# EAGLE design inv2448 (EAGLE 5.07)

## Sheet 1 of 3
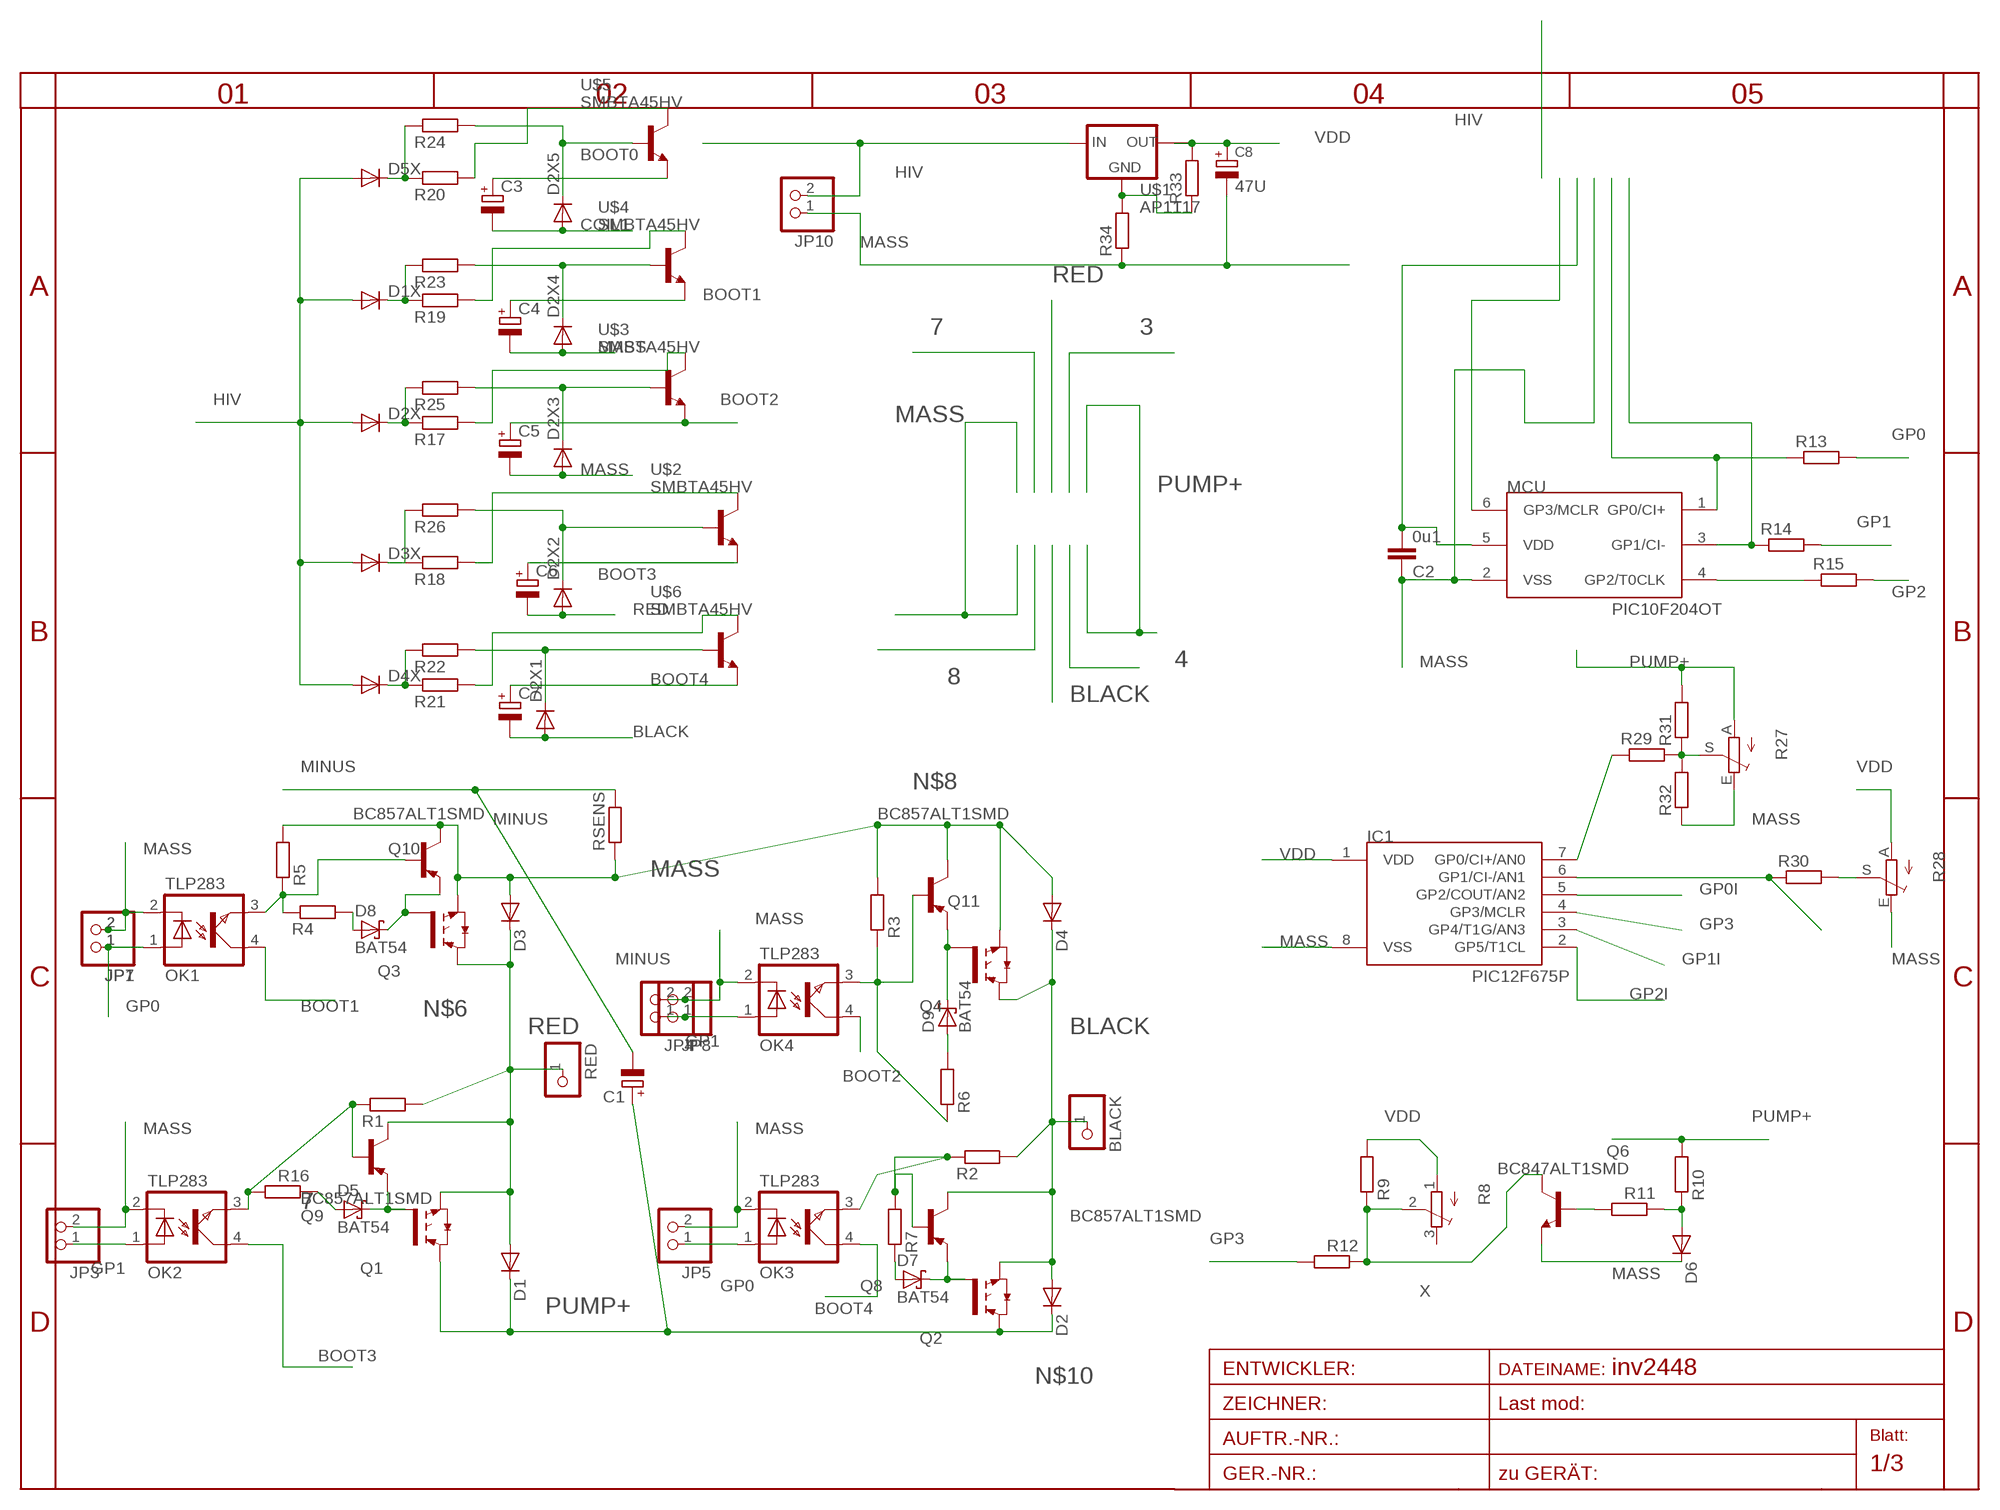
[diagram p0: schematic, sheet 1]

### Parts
BLACK  PINHD-1X14.5MM  [1X4MM5]
C1  CPOL-EUE5-13  [E5-13]
C2  0u1  C-EUC0805  [C0805]
C3  CPOL-EUE  [PANASONIC_E]
C4  CPOL-EUE  [PANASONIC_E]
C5  CPOL-EUE  [PANASONIC_E]
C6  CPOL-EUE  [PANASONIC_E]
C7  CPOL-EUE  [PANASONIC_E]
C8  47U  CPOL-EUC  [PANASONIC_C]
D1  DIODE-SMC  [SMC]
D1X  DIODE-SMA-DO214  [SMA-DO214AC]
D2  DIODE-SMC  [SMC]
D2X  DIODE-SMA-DO214  [SMA-DO214AC]
D2X1  DIODE-MINIMELF  [MINIMELF]
D2X2  DIODE-MINIMELF  [MINIMELF]
D2X3  DIODE-MINIMELF  [MINIMELF]
D2X4  DIODE-MINIMELF  [MINIMELF]
D2X5  DIODE-MINIMELF  [MINIMELF]
D3  DIODE-SMC  [SMC]
D3X  DIODE-SMA-DO214  [SMA-DO214AC]
D4  DIODE-SMC  [SMC]
D4X  DIODE-SMA-DO214  [SMA-DO214AC]
D5  BAT54  [SOT23]
D5X  DIODE-SMA-DO214  [SMA-DO214AC]
D6  DIODE-MINIMELF  [MINIMELF]
D7  BAT54  [SOT23]
D8  BAT54  [SOT23]
D9  BAT54  [SOT23]
IC1  PIC12F675P  [DIL8]
JP1  PINHD-1X2STR  [1X02]
JP3  PINHD-1X2STR  [1X02]
JP4  PINHD-1X2STR  [1X02]
JP5  PINHD-1X2STR  [1X02]
JP7  PINHD-1X2STR  [1X02]
JP8  PINHD-1X2STR  [1X02]
JP10  PINHD-1X2STR  [1X02]
MCU  PIC10F204OT  [SOT23-6]
OK1  TLP283  TLP283FLAT  [FLAT-4]
OK2  TLP283  TLP283FLAT  [FLAT-4]
OK3  TLP283  TLP283FLAT  [FLAT-4]
OK4  TLP283  TLP283FLAT  [FLAT-4]
Q1  IRG4BC15UD-S  [D2PACK]
Q2  IRG4BC15UD-S  [D2PACK]
Q3  IRG4BC15UD-S  [D2PACK]
Q4  IRG4BC15UD-S  [D2PACK]
Q6  BC847ALT1SMD  [SOT23]
Q8  BC857ALT1SMD  [SOT23-BEC]
Q9  BC857ALT1SMD  [SOT23-BEC]
Q10  BC857ALT1SMD  [SOT23-BEC]
Q11  BC857ALT1SMD  [SOT23-BEC]
R1  R-EU_R1206  [R1206]
R2  R-EU_R1206  [R1206]
R3  R-EU_R1206  [R1206]
R4  R-EU_R0805  [R0805]
R5  R-EU_R1206  [R1206]
R6  R-EU_R1206  [R1206]
R7  R-EU_R1206  [R1206]
R8  TRIM_EU-3223W  [3223W]
R9  R-EU_R1206  [R1206]
R10  R-EU_R1206  [R1206]
R11  R-EU_R1206  [R1206]
R12  R-EU_0204/7  [0204/7]
R13  R-EU_R0805  [R0805]
R14  R-EU_0207/10  [0207/10]
R15  R-EU_0207/20  [0207/20]
R16  R-EU_R1206  [R1206]
R17  R-EU_R1206  [R1206]
R18  R-EU_R1206  [R1206]
R19  R-EU_R1206  [R1206]
R20  R-EU_R1206  [R1206]
R21  R-EU_R1206  [R1206]
R22  R-EU_R1206  [R1206]
R23  R-EU_R1206  [R1206]
R24  R-EU_R1206  [R1206]
R25  R-EU_R1206  [R1206]
R26  R-EU_R1206  [R1206]
R27  TRIM_EU-RAND160  [RANDL]
R28  TRIM_EU-RAND160  [RANDL]
R29  R-EU_0207/30  [0207/30]
R30  R-EU_R0805  [R0805]
R31  R-EU_0207/30  [0207/30]
R32  R-EU_R0805  [R0805]
R33  R-EU_R0805  [R0805]
R34  R-EU_R0805  [R0805]
RED  PINHD-1X14.5MM  [1X4MM5]
RSENS  R-EU_CERAM50  [CERAM50]
U$1  AP1117  [SOT223]
U$2  SMBTA45HV  [SOT23HV]
U$3  SMBTA45HV  [SOT23HV]
U$4  SMBTA45HV  [SOT23HV]
U$5  SMBTA45HV  [SOT23HV]
U$6  SMBTA45HV  [SOT23HV]

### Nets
3: OK1.3(EMIT) Q10.B R4.1 R5.1
4: OK3.3(EMIT) Q8.B R2.1 R7.2
7: OK2.3(EMIT) Q9.B R1.1 R16.2
BLACK: BLACK.1 C7.- D2.A D2X1.A D4.C Q2.3(E) Q4.2(C) Q8.C R2.2
BOOT0: C3.+ U$5.2(E) ; also sheet 2
BOOT1: C4.+ OK1.4(COL) U$4.2(E)
BOOT2: C5.+ OK4.4(COL) U$3.2(E)
BOOT3: C6.+ OK2.4(COL) U$2.2(E)
BOOT4: C7.+ OK3.4(COL) U$6.2(E)
COIL1: C3.- D2X5.A ; also sheet 2
GP0: JP1.1 JP5.1 JP7.1 OK1.1(A) OK3.1(A) R13.2
GP0I: IC1.5(GP2/COUT/AN2) MCU.1(GP0/CI+) R13.1
GP1: JP3.1 JP4.1 JP8.1 OK2.1(A) OK4.1(A) R14.2
GP1I: IC1.3(GP4/T1G/AN3) MCU.3(GP1/CI-) R14.1
GP2: R15.2 ; also sheet 2
GP2I: IC1.2(GP5/T1CL) MCU.4(GP2/T0CLK) R15.1
GP3: IC1.4(GP3/MCLR) MCU.6(GP3/MCLR) R12.2
HIV: D1X.A D2X.A D3X.A D4X.A D5X.A JP10.2 U$1.3(IN) ; also sheet 2
MASS: C2.1 C4.- C5.- C8.- D2X3.A D2X4.A D3.A D4.A D6.C IC1.8(VSS) JP1.2 JP3.2 JP4.2 JP5.2 JP7.2 JP8.2 JP10.1 MCU.2(VSS) OK1.2(C) OK2.2(C) OK3.2(C) OK4.2(C) Q3.3(E) Q4.3(E) Q6.2(E) Q10.C Q11.C R3.2 R5.2 R27.E R28.E R32.1 R34.1 RSENS.1 ; also sheet 2
MINUS: C1.- RSENS.2 ; also sheet 2,3
N$2: D8.1(A) R4.2
N$4: D6.A R10.1 R11.1
N$5: Q6.1(B) R11.2
N$6: D8.3(C) Q3.1(G) Q10.E
N$7: D9.3(C) Q4.1(G) Q11.E
N$8: OK4.3(EMIT) Q11.B R3.1 R6.1
N$9: D9.1(A) R6.2
N$10: D7.3(C) Q2.1(G) Q8.E
N$11: D7.1(A) R7.1
N$12: D5.1(A) R16.1
N$13: D3X.K(C) R18.1 R26.1
N$14: D5.3(C) Q1.1(G) Q9.E
N$15: D4X.K(C) R21.1 R22.1
N$16: D2X.K(C) R17.1 R25.1
N$17: D1X.K(C) R19.1 R23.1
N$18: D5X.K(C) R20.1 R24.1
N$19: D2X1.C R22.2 U$6.1(B)
N$20: D2X5.C R24.2 U$5.1(B)
N$21: D2X4.C R23.2 U$4.1(B)
N$22: D2X2.C R26.2 U$2.1(B)
N$23: D2X3.C R25.2 U$3.1(B)
N$24: R28.S R30.2
N$25: R18.2 U$2.3(C)
N$26: R21.2 U$6.3(C)
N$27: R17.2 U$3.3(C)
N$28: R20.2 U$5.3(C)
N$29: R19.2 U$4.3(C)
N$30: R33.1 R34.2 U$1.1(GND)
N$31: IC1.6(GP1/CI-/AN1) R30.1
N$34: R27.S R29.2 R31.1 R32.2
N$35: IC1.7(GP0/CI+/AN0) R29.1
PUMP+: C1.+ D1.C D2.C Q1.2(C) Q2.2(C) R10.2 R27.A R31.2 ; also sheet 2,3
RED: C6.- D1.A D2X2.A D3.C Q1.3(E) Q3.2(C) Q9.C R1.2 RED.1
VDD: C2.2 C8.+ IC1.1(VDD) MCU.5(VDD) R8.1(A) R9.2 R28.A R33.2 U$1.2(OUT) U$1.4(TAB)
X: Q6.3(C) R8.2(S) R9.1 R12.1
Unconnected: R8.3(E)

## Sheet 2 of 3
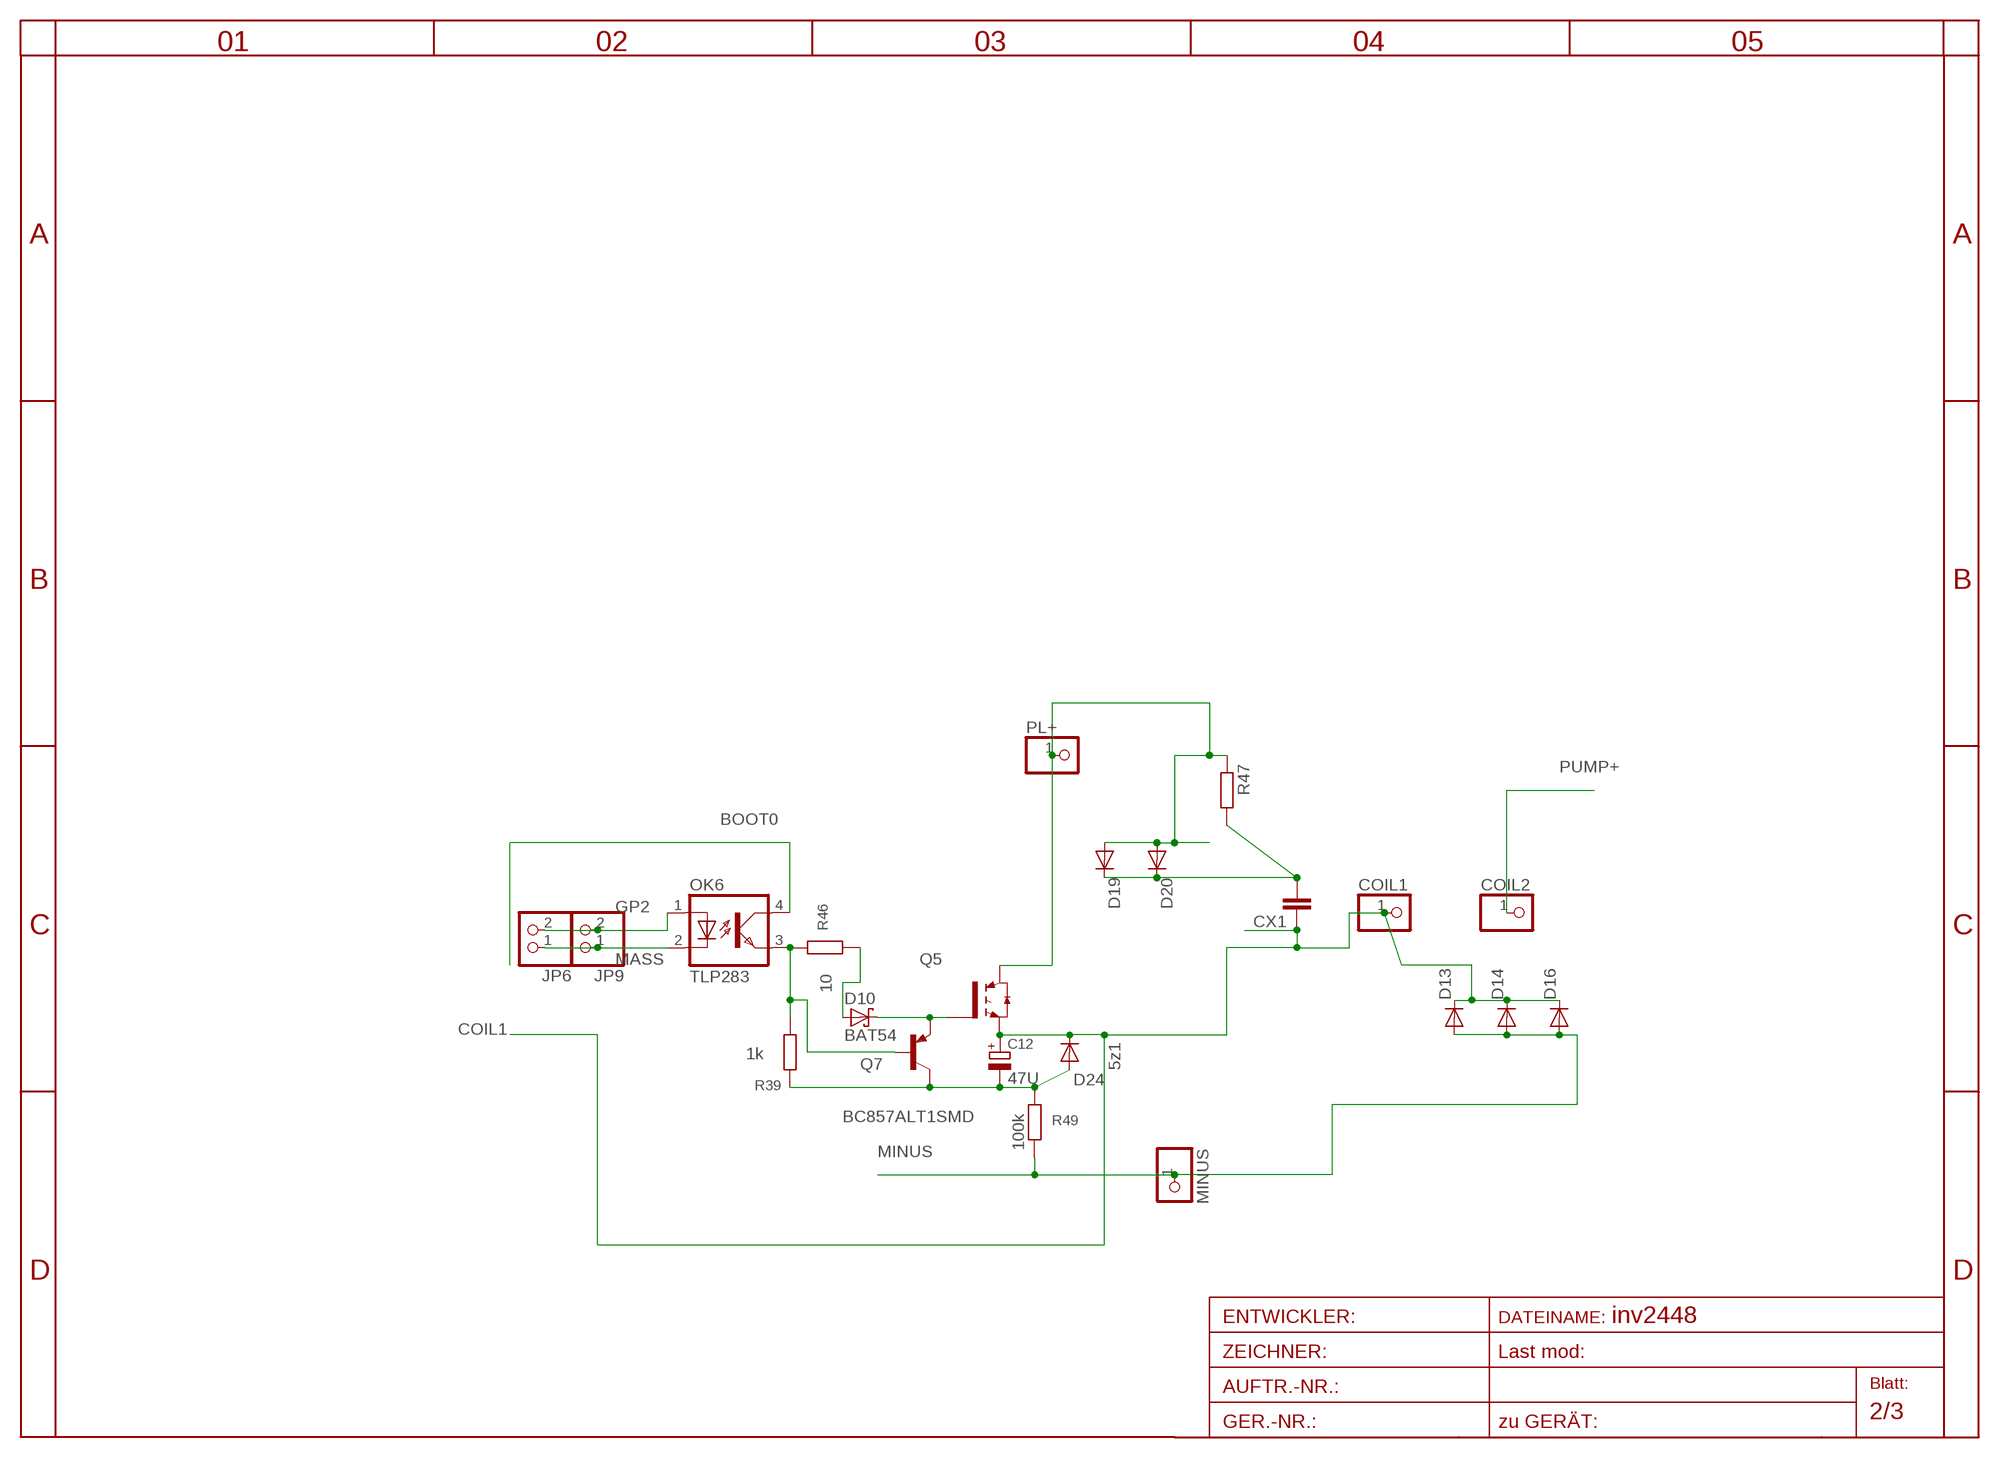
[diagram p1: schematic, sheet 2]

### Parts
C12  47U  CPOL-EUSMCA  [SMC_A]
COIL1  PINHD-1X14.5MM  [1X4MM5]
COIL2  PINHD-1X14.5MM  [1X4MM5]
CX1  CXXC22B10  [XC22B10]
D10  BAT54  [SOT23]
D13  DIODE-SMC  [SMC]
D14  DIODE-SMC  [SMC]
D16  DIODE-SMC  [SMC]
D19  DIODE-SMC  [SMC]
D20  DIODE-SMC  [SMC]
D24  5z1  DIODE-MINIMELF  [MINIMELF]
JP6  PINHD-1X2STR  [1X02]
JP9  PINHD-1X2STR  [1X02]
MINUS  PINHD-1X14.5MM  [1X4MM5]
OK6  TLP283  TLP283FLAT  [FLAT-4]
PL+  PINHD-1X14.5MM  [1X4MM5]
Q5  IRG4BC15UD-S  [D2PACK]
Q7  BC857ALT1SMD  [SOT23-BEC]
R39  1k  R-EU_R1206  [R1206]
R46  10  R-EU_R1206  [R1206]
R47  R-EU_0207/5V  [0207/5V]
R49  100k  R-EU_R1206  [R1206]

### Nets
BATT-: C12.- D24.A Q7.C R39.1 R49.2
BOOT0: OK6.4(COL) ; also sheet 1
COIL1: C12.+ COIL1.1 CX1.1 D13.C D14.C D16.C D24.C Q5.3(E) ; also sheet 1
GP2: JP6.2 JP9.2 OK6.1(A) ; also sheet 1
HIV: D19.A D20.A PL+.1 Q5.2(C) R47.1 ; also sheet 1
MASS: JP6.1 JP9.1 OK6.2(C) ; also sheet 1
MINUS: D13.A D14.A D16.A MINUS.1 R49.1 ; also sheet 1,3
N$1: D10.3(C) Q5.1(G) Q7.E
N$3: D10.1(A) R46.1
N$43: OK6.3(EMIT) Q7.B R39.2 R46.2
PUMP+: COIL2.1 ; also sheet 1,3
SNUB: CX1.2 D19.C D20.C R47.2

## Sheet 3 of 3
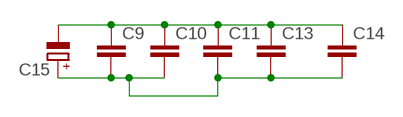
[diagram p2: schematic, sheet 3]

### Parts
C9  C-EUC1206  [C1206]
C10  C-EUC1206  [C1206]
C11  C-EUC1206  [C1206]
C13  C-EUC1206  [C1206]
C14  C-EUC1206  [C1206]
C15  CPOL-EUE2.5-7  [E2,5-7]

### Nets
MINUS: C9.1 C10.1 C11.1 C13.1 C14.1 C15.- ; also sheet 1,2
PUMP+: C9.2 C10.2 C11.2 C13.2 C14.2 C15.+ ; also sheet 1,2

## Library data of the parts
BLACK COIL1 COIL2 MINUS PL+ RED = pinhead:PINHD-1X1: PIN HEADER
C1 C3-C7 C15 = rcl:CPOL-EU: POLARIZED CAPACITOR, European symbol
C2 C9-C11 C13 C14 = rcl:C-EU: CAPACITOR, European symbol
C8 C12 = rcl-2:CPOL-EU: POLARIZED CAPACITOR, European symbol
CX1 = rcl:CX: X CAPACITOR
D1 D1X D2 D2X D2X1-D2X5 D3 D3X D4 D4X D5X D6 D13 D14 D16 D19 D20 D24 = diode:DIODE-: DIODE
D5 D7-D10 = diode:BAT54: Schottky Diodes
IC1 = microchip-5:PIC12F6*: uPC nW 1k Program Flash memory 2x Timer Comparator 10b A/D converter/ 4xIN
JP1 JP3-JP10 = pinhead:PINHD-1X2: PIN HEADER
MCU = microchip-3:PIC10F2*: uPC nW 0,25/0,5k Program Flash memory Comparator
OK1-OK4 OK6 = optocoupler:TLP283: TOSHIBA PHOTOCOUPLER GaAs IRED & PHOTO-TRANSISTOR Source: http://www.semicon.toshiba.co.jp/td/en/Opto/Photocoupler/en_20050928_TLP283_datasheet.pdf
Q1-Q5 = transistor-power:IRG4BC15UD-: INSULATED GATE BIPOLAR TRANSISTOR WITH ULTRAFAST SOFT RECOVERY DIODE
Q6 = transistor-npn:BC847*: NPN Transistor
Q7-Q11 = transistor-pnp:BC857*: PNP Transistror
R1-R7 R9-R12 R16-R26 R47 RSENS = rcl:R-EU_: RESISTOR, European symbol
R8 R27 R28 = pot:TRIM_EU-: POTENTIOMETER
R13-R15 R29-R34 R39 R46 R49 = rcl-2:R-EU_: RESISTOR, European symbol
U$1 = v-reg:AP1117
U$2-U$6 = transistor-npn:SMBTA45

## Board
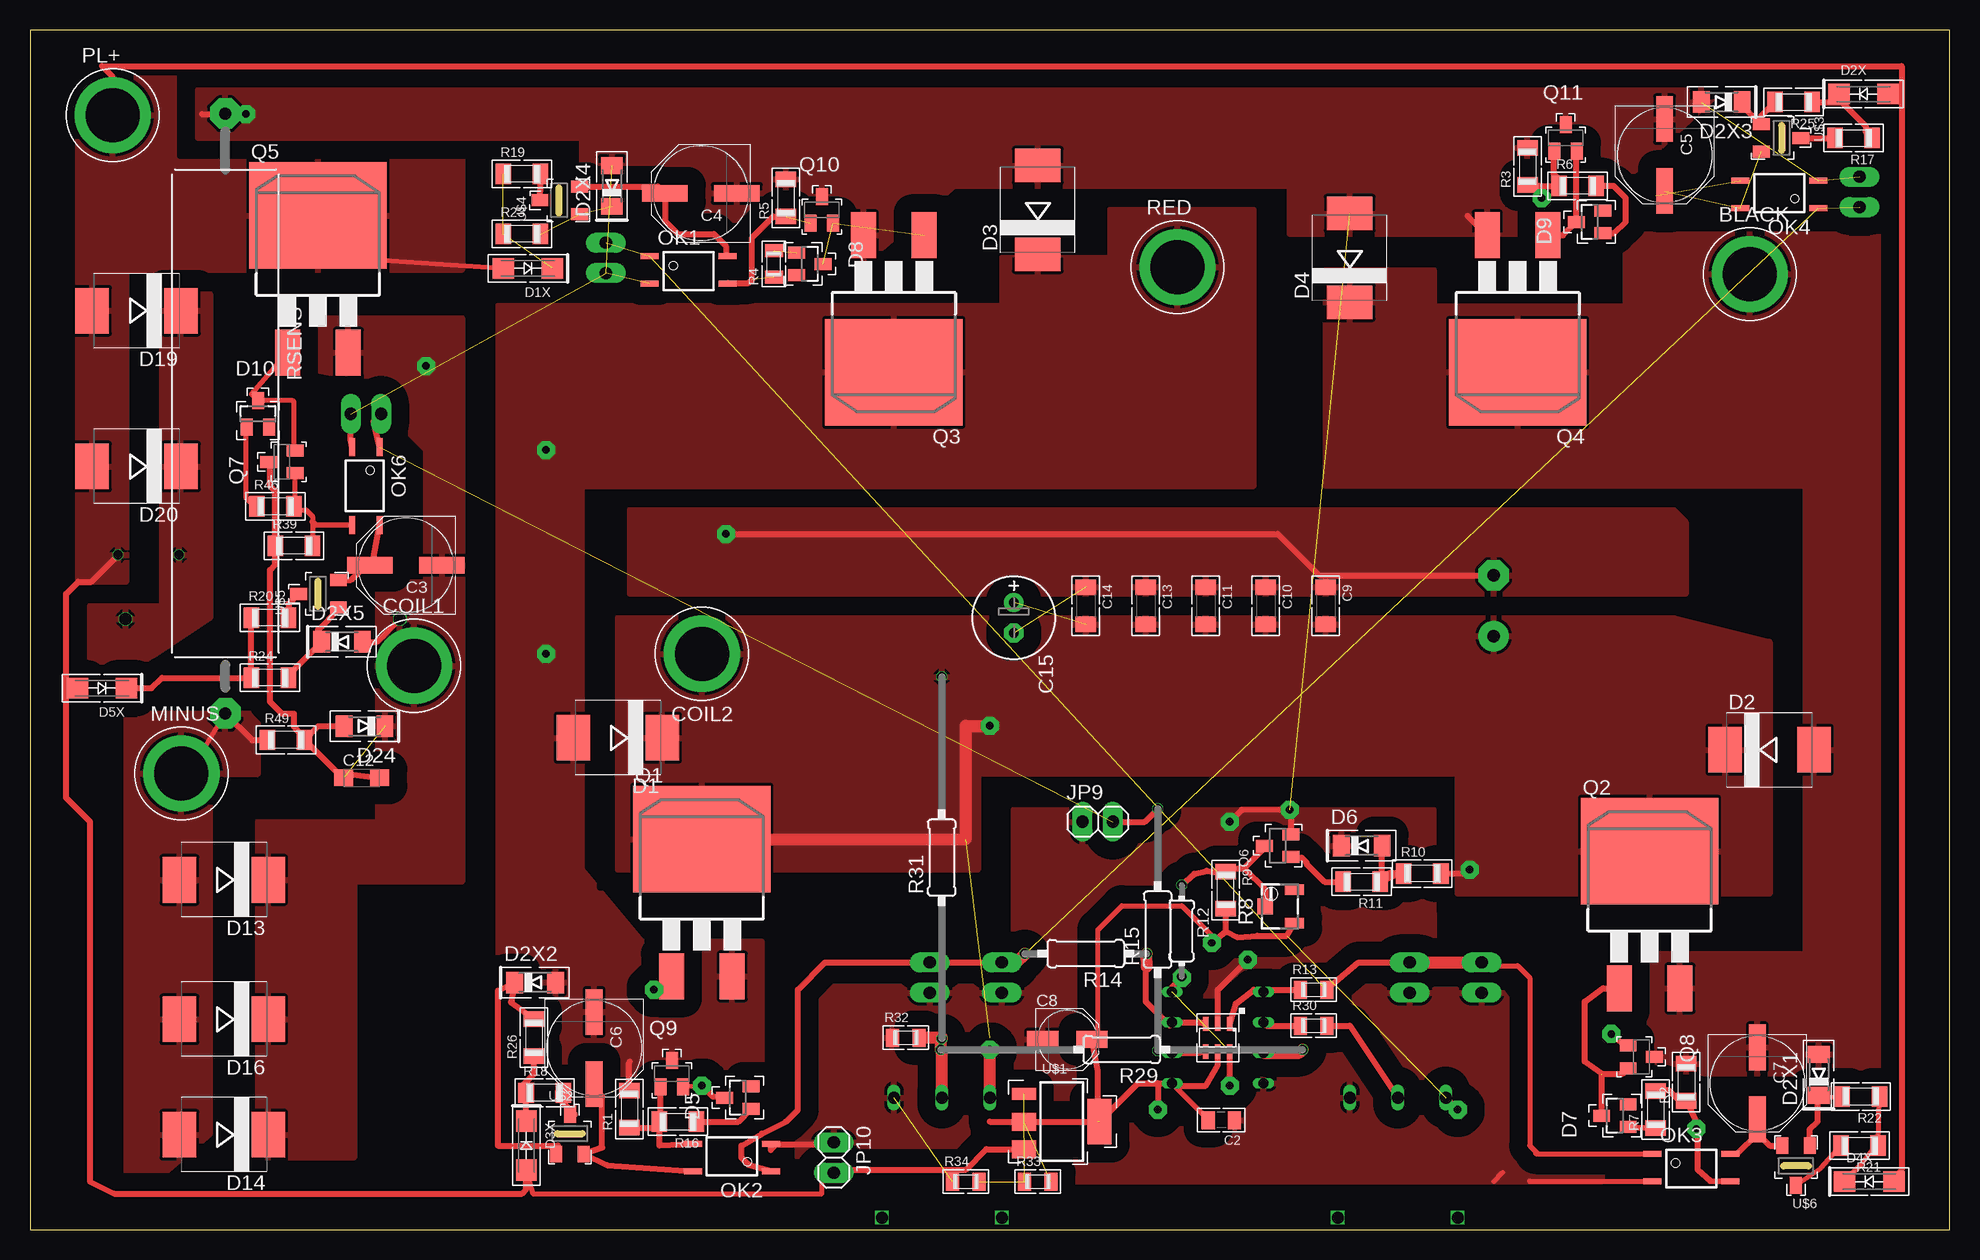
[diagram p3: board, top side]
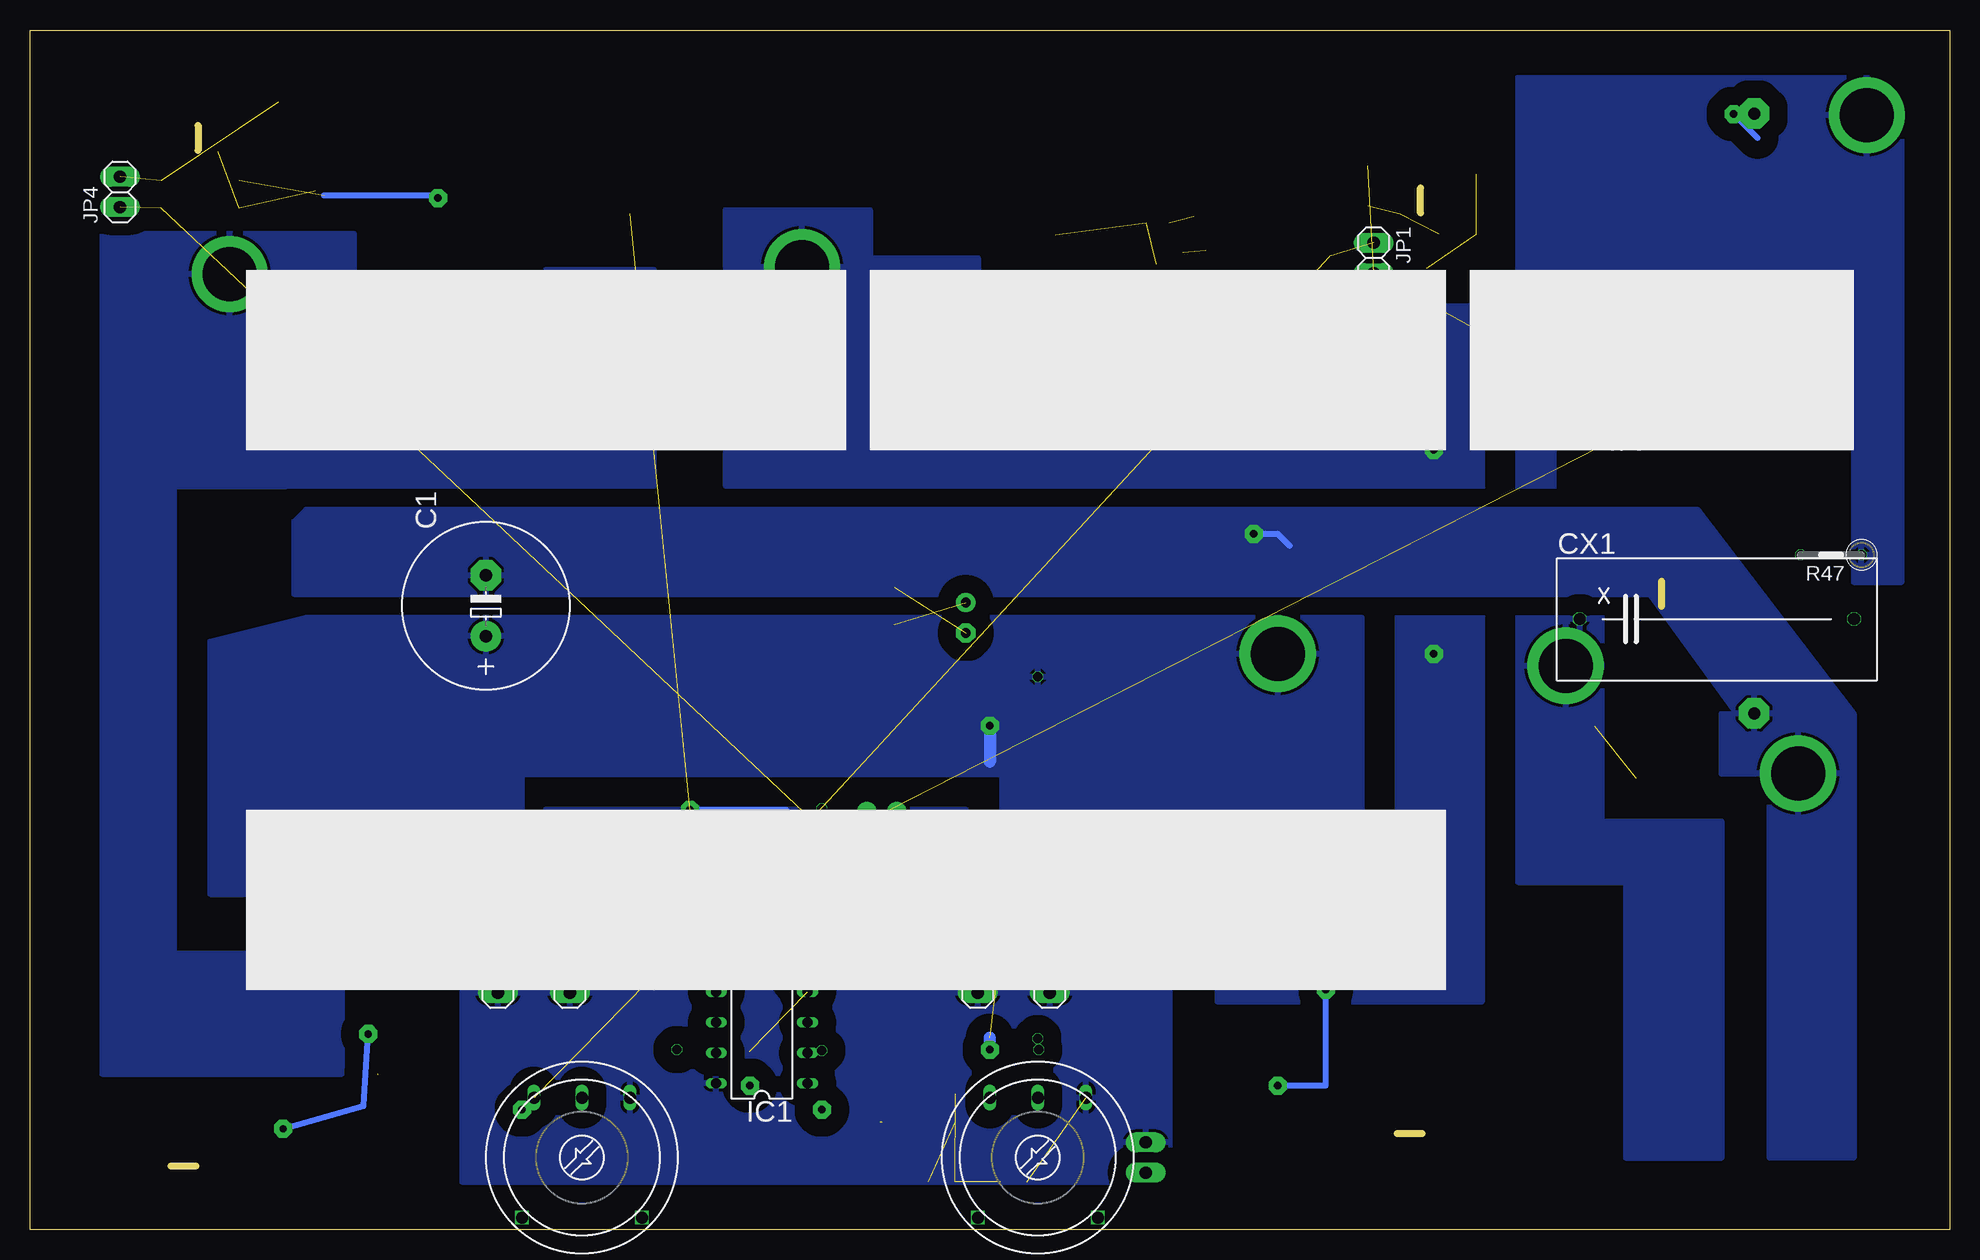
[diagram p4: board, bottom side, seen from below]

Size 160 x 100 mm. Coordinates in mm from the lower left corner, seen from the top.
Outline: 0,0 160,0 160,100 0,100 0,0
Copper layers (1*16): Top 0.035mm / dielectric 1.5mm / Bottom 0.035mm
Design rules "default": minimum track width 10mil, minimum drill 20mil, track to track 8mil, track to pad 8mil, pad to pad 8mil, via to via 8mil, smd to smd 8mil, copper to edge 40mil, drill to drill 8mil, minimum pad ring 1mil, minimum via ring 8mil, stop-mask expansion 4mil, vias tented up to drill 0mil, thermal gap 10mil

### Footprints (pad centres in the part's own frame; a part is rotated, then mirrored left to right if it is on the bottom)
1X4MM5 = drill 4.5 pad 6.35 round: 1 0,0
E5-13 = drill 1.016 pad 2.54 round: + -2.54,0 | drill 1.016 pad 2.54 octagon: - 2.54,0
C0805 = smd 1.1 x 1.5: 1 -1.1,0; 2 1.1,0
PANASONIC_E = smd 3.8 x 1.4: + 3,0; - -3,0
PANASONIC_C = smd 2.6 x 1.4: + 2.05,0; - -2.05,0
C1206 = smd 1.3 x 1.7: 1 -1.55,0; 2 1.55,0
SMC_A = smd 1.6 x 1.4: + -1.5,0; - 1.5,0
E2,5-7 = drill 0.813 pad 1.6 round: + -1.27,0 | drill 0.813 pad 1.6 octagon: - 1.27,0
XC22B10 = drill 1.016 octagon: 1 -11.43,0.025; 2 11.43,0.025
SMC = smd 2.8 x 3.8: A 3.7,0; C -3.7,0
SMA-DO214AC = smd 1.8 x 1.7: A 2.05,-0.127; K -2.05,-0.127
MINIMELF = smd 1.4 x 1.8: A 1.7,0; C -1.7,0
SOT23 = smd 1 x 1.4: 1 -0.95,-1.1; 2 0.95,-1.1; 3 0,1.1
DIL8 = drill 0.8 long: 1 -3.81,-3.81; 2 -1.27,-3.81; 3 1.27,-3.81; 4 3.81,-3.81; 5 3.81,3.81; 6 1.27,3.81; 7 -1.27,3.81; 8 -3.81,3.81
1X02 = drill 1.016 pad 1.676 long: 1 -1.27,0; 2 1.27,0
SOT23-6 = smd 0.45 x 1.2: 1 -1.016,-1.15; 2 0,-1.15; 3 1.016,-1.15; 4 1.016,1.15; 5 0,1.15; 6 -1.016,1.15
FLAT-4 = smd 1.5 x 0.5: 1 -3.25,1.15; 2 -3.25,-1.15; 3 3.25,-1.15; 4 3.25,1.15
D2PACK = smd 2.083 x 3.81: 1 -2.54,-8.89; 3 2.54,-8.89 | smd 11.43 x 8.89: 2 0,2.54
SOT23-BEC = smd 1 x 1.4: B -0.95,-1.1; C 0,1.1; E 0.95,-1.1
R1206 = smd 1.3 x 1.7: 1 -1.55,0; 2 1.55,0
R0805 = smd 1.1 x 1.5: 1 -1.1,0; 2 1.1,0
3223W = smd 0.9 x 1.6: 1 -1.4,-1.215; 3 1.4,-1.215 | smd 1.3 x 1.3: 2 0,1.215
0204/7 = drill 0.813 octagon: 1 -3.81,0; 2 3.81,0
0207/10 = drill 0.813 octagon: 1 -5.08,0; 2 5.08,0
0207/20 = drill 0.813 octagon: 1 -10.08,0; 2 10.08,0
RANDL = drill 1 long: A -4,5; E 4,5; S 0,5 | drill 1 square: P$1 -5,-5; P$2 5,-5
0207/30 = drill 0.813 octagon: 1 -15.08,0; 2 15.08,0
0207/5V = drill 0.813 octagon: 1 -2.54,0; 2 2.54,0
CERAM50 = drill 1 pad 2.54 octagon: 1 -25,0; 2 25,0
SOT223 = smd 1 x 2: 1 -2.3,-3.15 | smd 1.5 x 2: 2 0,-3.15; 3 2.3,-3.15 | smd 3.8 x 2: 4 0,3.15
SOT23HV = smd 1 x 1.4: 1 -1.15,-1.7; 2 1.15,-1.7; 3 0,1.6

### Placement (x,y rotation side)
BLACK  143.35,79.64 0 top
C1  122,52 90 bottom
C2  99.3,9.12 180 top
C3  31.34,55.37 180 top
C4  55.92,86.38 180 top
C5  136.25,89.57 270 top
C6  47.02,15.13 270 top
C7  143.98,12.19 270 top
C8  86.46,15.85 0 top
C9  108,52 270 top
C10  103,52 270 top
C11  98,52 270 top
C12  27.65,37.66 0 top
C13  93,52 270 top
C14  88,52 270 top
C15  82,51 270 top
COIL1  32,47 0 top
COIL2  56,48 180 top
CX1  19.39,50.87 0 bottom
D1  49,41 180 top
D1X  41.5,80 180 top
D2  145,40 0 top
D2X  152.83,94.78 0 top
D2X1  149.1,12.9 90 top
D2X2  42.1,20.6 0 top
D2X3  141,94 180 top
D2X4  48.5,87 90 top
D2X5  26,49 0 top
D3  84,85 90 top
D3X  41.5,7 270 top
D4  110,81 90 top
D4X  153.31,4.12 0 top
D5  59,11 90 top
D5X  6,45 180 top
D6  111,32 0 top
D7  132.1,9.5 90 top
D8  65,80.5 270 top
D9  130,84 90 top
D10  19,68 0 top
D13  16.16,29.15 180 top
D14  16.16,7.91 180 top
D16  16.16,17.53 180 top
D19  8.88,76.59 180 top
D20  8.88,63.62 180 top
D24  27.89,41.96 180 top
IC1  99,16 90 bottom
JP1  48,81 270 bottom
JP3  75,21 270 bottom
JP4  152.5,86.5 90 bottom
JP5  121,21 270 bottom
JP6  28,68 180 bottom
JP7  115,21 270 bottom
JP8  81,21 270 bottom
JP9  89,34 0 top
JP10  67,6 270 top
MCU  99,16 180 top
MINUS  12.62,38.02 0 top
OK1  54.9,80 0 top
OK2  58.5,6 180 top
OK3  138.46,5.18 0 top
OK4  145.81,86.29 180 top
OK6  28,62 270 top
PL+  6.89,92.9 0 top
Q1  56,30 0 top
Q2  135,29 0 top
Q3  72,74 180 top
Q4  124,74 180 top
Q5  24,82 0 top
Q6  104,32 90 top
Q7  21,64 90 top
Q8  134.3,14.4 270 top
Q9  53.5,13 0 top
Q10  66,85 0 top
Q11  128,91 0 top
R1  49.95,10.05 90 top
R2  138.05,12.28 90 top
R3  124.83,88.62 90 top
R4  62,80.5 90 top
R5  63,86 90 top
R6  129,87 0 top
R7  135.5,10 90 top
R8  104.18,26.94 90 top
R9  99.67,28.3 270 top
R10  116.05,29.67 0 top
R11  111,29 180 top
R12  96,24.9 270 top
R13  107,20 0 top
R14  88,23 180 top
R15  94,25 90 top
R16  54,9 180 top
R17  152,91 180 top
R18  42.9,11.4 0 top
R19  41,88 0 top
R20  20,51 0 top
R21  152.5,7 180 top
R22  152.6,11.1 180 top
R23  41,83 0 top
R24  20,46 0 top
R25  147,94 180 top
R26  42,16 90 top
R27  76,6 0 bottom
R28  114,6 0 bottom
R29  91,15 180 top
R30  107,17 0 top
R31  76,31 90 top
R32  73,16 0 top
R33  84,4 0 top
R34  78,4 0 top
R39  22,57 0 top
R46  20.46,60.28 0 top
R47  9.88,56.24 180 bottom
R49  21.34,40.81 0 top
RED  95.65,80.23 0 top
RSENS  16.29,68.04 270 top
U$1  86,9 270 top
U$2  45,8 0 top
U$3  146,91 270 top
U$4  44.1,85.8 90 top
U$5  24,53 90 top
U$6  147.2,5.3 180 top

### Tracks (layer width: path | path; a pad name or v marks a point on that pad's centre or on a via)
3  (2 unrouted)
  Top 0.5: R5.1 61.95,84.45 60.2,82.7 60.2,79.2 59.9,78.9 58.2,78.9 OK1.3
4  (via drill 0.6 pad 1.5)
  Top 0.5: Q8.B 132.75,15.45 v131.8,16.3 | OK3.3 140.06,4.04 139,5 139,8.3 v138.9,8.4 138.9,8.98 R2.1 137.47,10.73 136.6,11.6 135.55,11.6 R7.2
  Bottom 0.5: v131.8,16.3 132.2,10.3 v138.9,8.4
7
  Top 0.5: R16.2 52.45,7 OK2.3 | R1.1 51.95,8.5 R16.2 | Q9.B 52.55,9.1 R16.2
BATT-
  Top 0.5: Q7.C 20,63.9 20,62 20.45,61.55 R39.1 20.45,55.45 20,55 20,44 21,43 22,43 22,41.92 R49.2 | D24.A 24.04,41.96 R49.2 | C12.- 25.6,38.1 R49.2
BLACK
  pour Top (isolate 1.5, rank 2): 108,80 117,80 117,77 133,77 133,83 154,83 154,13 134,13 134,23 148,23 148,62 108,62
  pour Bottom (isolate 1.5, rank 2): 108,80 117,80 117,77 133,77 133,83 154,83 154,13 134,13 134,23 148,23 148,62 108,62
BOOT0
  Top 0.5: 28.64,56.02 OK6.4 | 28.64,56.02 C3.+ | U$5.2 26.76,54.15 28.64,56.02
BOOT1
  Top 0.5: OK1.4 58,81.3 58,82 57,83 54,83 52.92,84.08 C4.+ 52.35,86.95 U$4.2
BOOT2  (2 unrouted)
BOOT3
  Top 0.5: OK2.4 48.09,5.37 U$2.2 47.7,6.85 47.7,11.1 47.02,11.78 C6.+
BOOT4
  Top 0.5: OK3.4 142.33,6.33 144,8 | 144,8 144,9.17 C7.+ | U$6.2 145,7 144,8
COIL1  (via drill 0.6 pad 1.5)  (1 unrouted)
  Top 0.5: D2X5.A 28.93,49 CX1.1
  other vias: 33,72
  pour Top (isolate 1.5, rank 2): 22,76 36,76 36,29 27,29 27,6 19,6 19,34 29,34 29,54 33,54 33,65 27,71 22,72
  pour Bottom (isolate 1.5, rank 2): 26,76 36,76 36,29 27,29 27,6 19,6 19,34 29,34 29,54 33,54 33,65 26,72
GP0  (2 unrouted)
  Top 0.406: 125.5,6.5 125,7 125,21 124,22 121.27,22 JP5.1 | 125.5,6.5 125.58,6.42 | OK3.1 125.5,6.33 125.5,6.5
  Top 0.5: R13.2 108,20 110.73,22.27 JP7.1
  Top 1: JP7.1 JP5.1
GP0I
  Top 0.5: MCU.1 100.52,18.82 102,20 102.62,20 IC1.5 103,20 R13.1
GP1  (2 unrouted)
  Top 0.5: 82.19,22.27 JP8.1 JP3.1 66.27,22.27 64,20 64,10 63,9 61,8 59.3,7 59.3,6 59.94,5.37 OK2.1
  Top 1: 82.19,22.27 R14.2
GP1I
  Top 0.5: MCU.3 97.6,17.27 IC1.3 95,17.08 95,17 93,19 93,21.9 93.1,21.9
  Top 1: 93.1,21.9 R14.1
GP2  (1 unrouted)
  Top 0.5: OK6.1 28.64,67.36 JP6.2 | JP9.2 92.92,34 R15.2
GP2I
  Top 0.5: MCU.4 97.36,14.73 IC1.2 95.19,14.81 95,15 94.08,15 R15.1
GP3  (via drill 0.6 pad 1.5)  (1 unrouted)
  Top 0.5: MCU.6 100.02,13.98 v100,12 | R12.2 96.2,21.2 v96,21 95.19,20.19 IC1.4
HIV
  Top 0.406: 66,5 66,3 41.9,3 D3X.A | 67,5 JP10.2 | D1X.A 27.62,80.92 Q5.2
  Top 0.5: D4X.A 155.44,4.44 156,5 156,95 | 156,95 156,97 6,97 6.89,96.11 PL+.1 | 3,45 3,36 5,34 5,4 7,3 41,3 41.37,3.37 D3X.A | 3,45 3,53 4,54 5.1,54 R47.1 | U$1.3 79.7,6.7 78,5 67,5 66,5 | D5X.A 3.13,45.13 3,45 | D2X.A 155.65,94.65 156,95
  pour Top (isolate 1.5, rank 2): 4,96 36,96 36,80 8,80 8,54 4,54
  pour Bottom (isolate 1.5, rank 2): 4,96 36,96 36,80 8,80 8,54 4,54
MASS  (via drill 0.6 pad 1.5)  (7 unrouted)
  Top 0.406: 122,4 122.75,4.75 | OK3.2 125,4.03 125,4
  Top 0.5: Q4.3 119.83,84.52 | MCU.2 99,20 v101.5,22.5 | Q6.2 105.1,34.9 v105,35 101,35 v100,34 | JP10.1 65.83,7.1 62.2,7.1 61.73,6.63 OK2.2 | JP6.1 26.73,65.88 OK6.2 | v18,93 14.33,93 RSENS.1
  Bottom 0.5: v105,35 97,35 92,30 | v18,93 16,91
  pour Top (isolate 1.5): 14,95 141,95 128,83 105,83 105,87 77,87 70,81 52,81 48,82 48,87 46,87 46,91 14,91
  pour Top (isolate 1.5, rank 3): 82,35 117,35 117,22 121,22 131,9 131,4 64,4 64,21 74,24 82,24
  pour Bottom (isolate 1.5, rank 3): 82,35 117,35 117,22 124,22 124,4 65,4 65,21 78,21 82,24
MINUS  (via drill 0.6 pad 1.5)  (1 unrouted)
  Top 0.406: RSENS.2 14.29,39.69 MINUS.1
  Top 0.5: C1.- 107.46,54.54 104,58 v58,58 | R49.1 18.52,40.81 RSENS.2
  Bottom 0.5: v58,58 56,58 55,57
  pour Top (isolate 1.5): 138,53 50,53 50,60 137,60 138,59
  pour Top (isolate 1.5, rank 3): 8,43 8,2 15,8 15,38 19,38 19,43
  pour Bottom (isolate 1.5): 8,43 21,60 60,60 60,53 25,53 17,42 9,42
  pour Bottom (isolate 1.5): 138,53 50,53 50,60 137,60 138,59
  pour Bottom (isolate 1.5, rank 3): 8,43 8,6 15,6 15,38 19,38 19,43
N$1
  Top 0.406: Q5.1 18.46,69.64 D10.3 21.9,69.1 22,69 22,65.05 Q7.E
N$2  (1 unrouted)
N$3
  Top 0.406: R46.1 18.72,60.28 18,61 18,66.85 D10.1
N$4
  Top 0.5: R10.1 113.22,29.67 114.28,29.73 | R11.1 114.28,29.73 | D6.A 112.7,29.3 114.28,29.73
N$5
  Top 0.5: R11.2 107.9,29 106.4,30.5 106.4,30.6 106,31 105.15,31 Q6.1
N$6  (2 unrouted)
N$7
  Top 0.5: Q4.1 127.79,82.89 D9.3 128.9,89.85 Q11.E
N$8  (via drill 0.6 pad 1.5)  (1 unrouted)
  Top 0.5: Q11.B 127,89.85 127,88 127.45,87.55 R6.1 126,87 | 126,87 124.9,87 R3.1 | v126,86 126,87
  Bottom 0.5: 135.5,86.2 126.2,86.2 v126,86
N$9
  Top 0.5: D9.1 132.05,83.05 133,84 133,86 132,87 R6.2
N$10  (1 unrouted)
  Top 0.5: Q2.1 131.11,20.11 129.6,19 129.6,14 131,13 132.75,13 Q8.E | D7.3 131,12.9
N$11
  Top 0.5: D7.1 R7.1
N$12
  Top 0.5: R16.1 59.05,9 D5.1
N$13
  Top 0.5: R26.1 42,13 41,12 41,11.75 R18.1 41.37,11.38 D3X.K
N$14  (via drill 0.6 pad 1.5)
  Top 0.406: Q9.E 56.05,12 v56,12
  Top 0.5: D5.3 56.9,11.1 v56,12 | v52,20 52.35,20 Q1.1
  Bottom 0.5: v56,12 52,12 v52,20
N$15
  Top 0.406: D4X.K 151.06,3.86 152.6,5.4 153.9,7.05 R21.1 R22.1
N$16
  Top 0.5: R25.1 150.43,94 | 150.43,94 D2X.K | 150.43,94 151,94 153,92 153,91.55 R17.1
N$17  (2 unrouted)
N$18
  Top 0.5: D5X.K 10.13,45.13 11,46 R24.1 R20.1
N$19
  Top 0.406: R22.2 149.3,11 D2X1.C
  Top 0.5: U$6.1 148.35,8.35 149,9 149,11.1 D2X1.C
N$20
  Top 0.5: R24.2 21.55,46.25 D2X5.C 24,49.3 24,50 25.7,51.7 U$5.1
N$21  (2 unrouted)
N$22
  Top 0.5: U$2.1 43.7,6.3 44,7 39,7 39,19.9 D2X2.C 40.1,18.95 R26.2
N$23
  Top 0.5: D2X3.C 142.7,93.75 U$3.1 144.3,92.85 R25.2
N$24
  Top 0.5: R28.S 110,17 R30.2
N$25
  Top 0.5: U$2.3 45.4,9.6 44,11 44,11.55 R18.2
N$26
  Top 0.406: U$6.3 149.25,5.1 R21.2
N$27
  Top 0.5: U$3.3 R17.2
N$28
  Top 0.5: R20.2 21.55,52.15 U$5.3
N$29
  Top 0.5: R19.2 42.55,87.15 U$4.3
N$30  (2 unrouted)
N$31
  Top 0.5: IC1.6 103.08,17 R30.1
N$34
  Top 1: R27.S 76,14.92 R29.2 75.92,15.92 R31.1 76,16 R32.2
N$35
  Top 1: IC1.7 105.81,14.73 R29.1
N$43
  Top 0.406: Q7.B 22.1,60.37 R46.2 22.29,60 23,60 23.55,59.45 23.55,59 R39.2
  Top 0.5: OK6.3 23.79,58.76 23.55,59
PUMP+  (via drill 0.6 pad 1.5)  (2 unrouted)
  Top 0.5: R10.2 119.67,29.67 v120,30
  Top 1: R27.A v80,15 | Q1.2 78,32.54 78,42 v80,42
  Bottom 1: v80,15 80,16 | v80,42 80,39
  pour Top (isolate 1.5): 145,49 145,28 119,28 119,38 79,38 79,30 49,30 49,51 137,51
  pour Bottom (isolate 1.5): 145,49 145,28 119,28 119,38 79,38 79,30 49,30 49,51 137,51
RED  (via drill 0.6 pad 1.5)
  Top 0.5: R1.2 49.95,13.95 50,14
  other vias: 43,65 43,48
  pour Top (isolate 1.5, rank 2): 102,62 102,85 90,85 90,81 81,81 81,77 39,77 39,13 61,13 61,24 51,24 46,30 46,62
  pour Bottom (isolate 1.5, rank 2): 102,62 102,85 90,85 90,81 81,81 81,77 39,77 39,19 61,19 61,24 51,24 46,30 46,62
SNUB
  pour Top (isolate 1.5, rank 2): 11,78 15,78 15,51 9,47 5,47 5,52 11,52
VDD  (via drill 0.6 pad 1.5)  (3 unrouted)
  Top 0.406: C2.2 98.2,9.18 IC1.1 | v98.5,23.9 98.5,24.5 96,27 91,27 89,25 89,16.34 C8.+
  Top 0.5: MCU.5 99,13.7 98,12 95.38,12 IC1.1 94,12.19 | 80,9 U$1.2 89,9 89,13.24 C8.+ | U$1.4 92.34,12.19 94,12.19 | v119,10 R28.A | 94,12.19 v94,10 | 99.67,24.87 R9.2 | v98.5,23.9 99.67,24.87 | 99.67,24.87 100.63,24.37 102.3,24.5 104.75,24.5 R8.1
X
  Top 0.5: R8.2 102.97,28.34 101.2,30.1 | 101.2,30.1 99.92,30.1 R9.1 99.52,29.7 98.1,29.9 97.05,29.65 R12.1 | Q6.3 102.9,31.8 101.2,30.1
